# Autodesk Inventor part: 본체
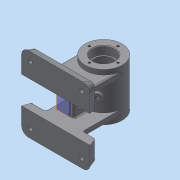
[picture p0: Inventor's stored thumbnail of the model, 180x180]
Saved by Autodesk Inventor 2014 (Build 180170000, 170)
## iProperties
Created: 2016-07
Part Number: 본체
Material: 일반
Document SubType Name: Modeling
Designer: 406-9
Density: 1 g/cm^3
Appearance: 기본값
Author: 406-9
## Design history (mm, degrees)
sketch "스케치1"
  geometry: L1 (-40, 55)-(40, 55); L2 (50, 45)-(50, -45); L3 (40, -55)-(-40, -55); L4 (-50, -45)-(-50, 45); L5 (-50, 55)-(50, -55); L6 (50, 55)-(-50, -55); A1 r 10 centre (-40, 45) between (-40, 55) and (-50, 45); A2 r 10 centre (40, 45) between (50, 45) and (40, 55); A3 r 10 centre (40, -45) between (40, -55) and (50, -45); A4 r 10 centre (-40, -45) between (-50, -45) and (-40, -55); 1 further point
  constraints: 12 end point, 8 point on circle, 8 point on line, 8 tangent, 4 centre point, 3 equal radius, 2 midpoint, 2 parallel, 1 horizontal, 1 perpendicular
  dimensions: "d0" = 100 distance of L5.end L6.end; "d1" = 110 distance of L6.end L5.start; "d119" = 10 radius of A1
sketch "스케치3"
  geometry: C1 r 27 at (0, 70); 1 further point
  constraints: 1 centre point, 1 vertical alignment
  dimensions: "d5" = 54 diameter of C1; "d6" = 70 distance of point (0, 0) C1.centre
extrude "돌출2" join sketch "스케치3" stored distance "d7" = 70; taper "d8" = 0 deg
node "작업 평면2"
sketch "스케치5"
  geometry: L1 (27, 35)-(-27, 35) reference; L2 (-27, -35)-(27, -35) reference; L3 (0, 35)-(0, -35); L4 (0, 35)-(-16, 35); L5 (-16, 35)-(-16, 23.3); L6 (-15.7, 23)-(-14, 23); L7 (-14, 23)-(-14, 21); L8 (-14, 21)-(-19, 21); L9 (-22, 18)-(-22, -18); L10 (-19, -21)-(-14, -21); L11 (-14, -21)-(-14, -23); L12 (-14, -23)-(-15.7, -23); L13 (-16, -23.3)-(-16, -35); L14 (0, -35)-(-16, -35); A1 r 3 centre (-19, -18) between (-22, -18) and (-19, -21); A2 r 3 centre (-19, 18) between (-19, 21) and (-22, 18); A3 r 0.3 centre (-15.7, -23.3) between (-15.7, -23) and (-16, -23.3); A4 r 0.3 centre (-15.7, 23.3) between (-16, 23.3) and (-15.7, 23); 5 further points
  constraints: 24 end point, 9 point on line, 8 point on circle, 8 tangent, 5 perpendicular, 4 centre point, 4 parallel, 2 collinear, 2 equal radius, 2 midpoint, 1 horizontal, 1 vertical
  dimensions: "d19" = 32 diameter of L5 L3; "d20" = 28 diameter of L7 L3; "d21" = 44 diameter of L9 L3; "d22" = 42 distance of point (-22, 21) point (-22, -21); "d23" = 12 distance of L4.end point (-16, 23); "d24" = 12 distance of point (-16, -23) L13.end; "d25" = 2 distance of L10.end L11.end; "d27" = 3 radius of A1; "d28" = 0.3 radius of A3
revolve "회전1" sketch "스케치5" stored, may be unused: angle "d26" = 90 deg
sketch "스케치6" dims "d29" = 42
  geometry: C1 r 16 at (0, 0) reference; 3 further points
  constraints: 2 vertical alignment, 1 coincident, 2 other
hole "구멍1" sketch "스케치6" at (0, 21) diameter "d30" = 3.242; stored, may be unused: countersink angle "d34" = 90 deg, drill point angle "d36" = 118 deg; dims "d31" = 8, "d32" = 4, "d33" = 2, "d35" = 10
sketch "스케치7"
  geometry: L1 (-27, 70)-(27, 70); L2 (0, 70)-(15.898, 44.559); L3 (0, 97)-(0, 43); L4 (15.898, 44.559)-(20.986, 47.738); L5 (20.986, 47.738)-(17.806, 52.826); L6 (17.806, 52.826)-(12.718, 49.647); A1 r 27 centre (0, 70) between (-27, 70) and (27, 70) reference; 1 further point
  constraints: 12 end point, 4 perpendicular, 4 point on circle, 2 midpoint, 1 coincident, 1 horizontal, 1 point on line
  dimensions: "d40" = 30 distance of L2.start L2.end; "d41" = 32 deg angle of L3 L2; "d42" = 12 diameter of L5 L2; "d43" = 6 distance of L4.end L5.end
node "작업 평면5"
sketch "스케치10"
  geometry: L1 (43, -35)-(43, 35) reference; L2 (43, -20)-(22, -20); L3 (22, -20)-(22, 20); L4 (22, 20)-(43, 20); L5 (43, 20)-(43, -20); L6 (32, -8)-(32, 8); L7 (35.5, -8)-(35.5, 8); L8 (28.5, 8)-(28.5, -8); A1 r 3.5 centre (32, -8) between (28.5, -8) and (35.5, -8); A2 r 3.5 centre (32, 8) between (35.5, 8) and (28.5, 8); 2 further points
  constraints: 16 end point, 4 parallel, 4 point on circle, 4 tangent, 2 centre point, 1 horizontal, 1 horizontal alignment, 1 midpoint, 1 perpendicular, 1 point on line
  dimensions: "d61" = 21 distance of L3.end L4.end; "d62" = 32 distance of point (0, 0) point (32, 0); "d64" = 3.5 radius of A2; "d65" = 23 dimension on A2 A1
node "작업 평면3"
sketch "스케치11"
  geometry: C1 r 5 at (0, 0); 1 further point
  constraints: 1 centre point, 1 coincident
  dimensions: "d69" = 10 diameter of C1
extrude "돌출6" join sketch "스케치11" stored distance "d70" = 8; taper "d71" = 0 deg
hole "구멍3" diameter "d74" = 5.188; stored, may be unused: countersink angle "d78" = 90 deg, drill point angle "d80" = 118 deg; dims "d72" = 10, "d73" = 10, "d75" = 8, "d76" = 4, "d77" = 2, "d79" = 10
node "작업 평면4"
node "작업 평면6"
extrude "돌출7" join sketch "스케치1" distance "d120" = 12; taper "d121" = -20 deg
sketch "스케치17"
  geometry: L1 (27, -28)-(-27, -28); L2 (-27, -28)-(-27, 28); L3 (-27, 28)-(27, 28); L4 (27, 28)-(27, -28); L5 (27, -28)-(-27, 28); L6 (-27, -28)-(27, 28); L7 (-40, 55)-(40, 55) reference; 1 further point
  constraints: 12 end point, 2 midpoint, 2 parallel, 1 horizontal, 1 perpendicular
  dimensions: "d124" = 27 distance between parallel lines of L7 L3; "d125" = 54 distance of L1.start L1.end
extrude "돌출9" join sketch "스케치17" stored distance "d126" = 8; taper "d127" = 0 deg
sketch "스케치18"
  geometry: L1 (27, 12)-(27, 70) reference; L2 (-27, 12)-(27, 12) reference; L3 (-27, 12)-(-27, 70) reference; L4 (-45.632, 12)-(-40, 12) reference; L5 (-40, 0)-(-40, 12) reference; L6 (-50, 0)-(-40, 0) reference; L7 (-50, 0)-(-45.632, 12) reference; L8 (-40, 12)-(40, 12) reference; L9 (40, 0)-(40, 12) reference; L10 (-40, 0)-(40, 0) reference; L11 (-40, 0)-(-40, 12) reference; L12 (40, 12)-(45.632, 12) reference; L13 (50, 0)-(45.632, 12) reference; L14 (40, 0)-(50, 0) reference; L15 (40, 0)-(40, 12) reference; A1 r 27 centre (0, 70) between (-27, 70) and (27, 70) reference; 1 further point
extrude "돌출10" cut sketch "스케치18" stored distance "d128" = 40; taper "d129" = 0 deg
revolve "회전4" stored, may be unused: angle "d130" = 90 deg
hole "구멍6" diameter "d133" = 5.188; stored, may be unused: countersink angle "d137" = 90 deg, drill point angle "d139" = 118 deg; dims "d131" = 10, "d132" = 10, "d134" = 8, "d135" = 19.05, "d136" = 4.775, "d138" = 10
extrude "돌출8" join sketch "스케치10" stored distance "d122" = 8; taper "d123" = 0 deg
sketch "스케치19"
  geometry: 5 further points
  constraints: 2 horizontal alignment, 2 vertical alignment
  dimensions: "d140" = 75 distance of point (-37.5, 42.5) point (37.5, 42.5); "d141" = 85 distance of point (-37.5, 42.5) point (-37.5, -42.5); "d142" = 37.5 horizontal distance of point (-37.5, 42.5) point (0, 0); "d143" = 42.5 vertical distance of point (-37.5, 42.5) point (0, 0)
hole "구멍7" sketch "스케치19" at (-37.5, 42.5), (37.5, 42.5), (37.5, -42.5), (-37.5, -42.5) diameter "d144" = 6; stored, may be unused: countersink angle "d148" = 90 deg, drill point angle "d150" = 118 deg; dims "d145" = 8, "d146" = 10, "d147" = 4, "d149" = 10
fillet "모깎기1" dims "d151" = 2
chamfer "모따기1" distance "d152" = 1; stored, may be unused: second distance "d153" = 2, angle "d154" = 45 deg
node "작업 평면7"
sketch "스케치20"
  geometry: L1 (-27, -35)-(27, -35) reference; L2 (-27, -35)-(-27, 35) reference; 2 further points
  constraints: 1 other
  dimensions: "d155" = 35 distance from line of L1 point (0, 0); "d156" = 27 distance from line of L2 point (0, 0)
feature "엠보싱1" sketch "스케치20" dims "d0" = 100, "d1" = 110, "d19" = 32, "d20" = 28, "d21" = 44, "d22" = 42, "d23" = 12, "d24" = 12, "d25" = 2, "d27" = 3, "d28" = 0.3, "d119" = 10, "d157" = 0.5, "d158" = 0
node "솔리드1"
pattern_circular "원형 패턴1" dims angle "d38" = 360 deg
mirror "대칭1"
node "투영된 루프2"
node "투영된 루프3"
node "투영된 루프4"
node "투영된 루프5"
other parameters: "d103" = 12
